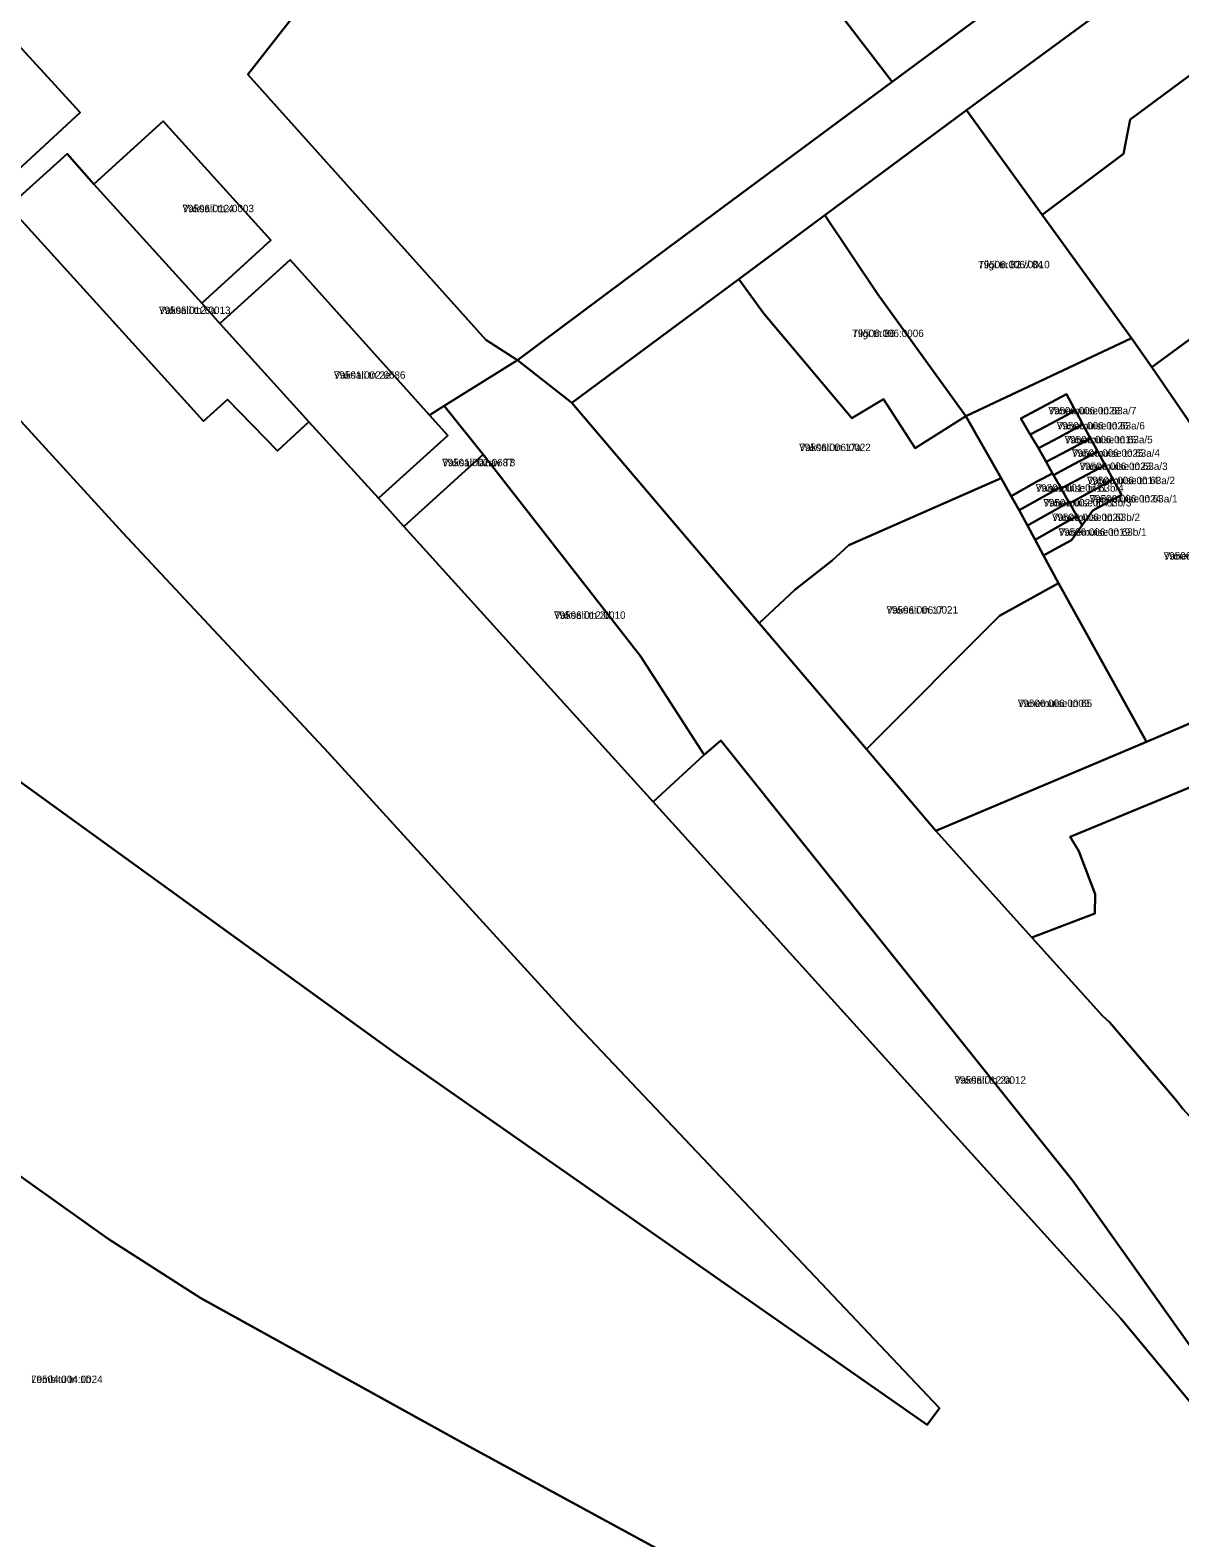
# Model space of a CAD drawing. Extents: x 643847 to 663718, y 6468443 to 6482775.
# Drawn here: x 658356.7 to 658589.8, y 6473255.6 to 6473561.4 of the extents above; entities that cross this region are included whole.
import ezdxf

# ---------------------------------------------------------------- set-up
doc = ezdxf.new("R2010")
doc.units = 0
for name, color, linetype in [('L_AADRESS', 7, 'Continuous'), ('PIIR', 7, 'Continuous'), ('TUNNUS', 7, 'Continuous')]:
    doc.layers.add(name, color=color, linetype=linetype)

msp = doc.modelspace()

# ---------------------------------------------------------------- linework, layer by layer
at = {"layer": 'PIIR'}
for points in [[(658099.05, 6473750.83), (658151.22, 6473704.05), (658244.25, 6473602.92), (658338.37, 6473500.05), (658375.52, 6473459.45), (658417.14, 6473414.88), (658466.64, 6473360.53), (658541.04, 6473281.9), (658538.55, 6473278.55), (658431.43, 6473353.39), (658331.84, 6473425.43), (658302.17, 6473447.92), (658262.57, 6473482.37), (658235.33, 6473509.39), (658193.26, 6473561.37), (658156.4, 6473618.75), (658128.89, 6473663.26), (658084.14, 6473738.99)], [(658099.05, 6473750.83), (658084.14, 6473738.99), (658128.89, 6473663.26), (658156.4, 6473618.75), (658193.26, 6473561.37), (658235.33, 6473509.39), (658262.57, 6473482.37), (658302.17, 6473447.92), (658331.84, 6473425.43), (658431.43, 6473353.39), (658538.55, 6473278.55), (658541.04, 6473281.9), (658466.64, 6473360.53), (658417.14, 6473414.88), (658375.52, 6473459.45), (658338.37, 6473500.05), (658244.25, 6473602.92), (658151.22, 6473704.05)], [(658618.85, 6473614.88), (658643.21, 6473632.41), (658650.48, 6473639.87), (658656.84, 6473626.22), (658646.06, 6473618.28), (658632.45, 6473608.26), (658596.39, 6473581.8), (658546.58, 6473545.17), (658517.84, 6473523.87), (658500.37, 6473510.91), (658466.51, 6473485.81), (658455.5, 6473494.46), (658486.16, 6473517.32), (658531.46, 6473550.91), (658557.16, 6473569.99), (658611.19, 6473609.32)], [(658557.16, 6473569.99), (658531.46, 6473550.91), (658503.12, 6473587.99), (658507.61, 6473591.43), (658515.13, 6473597.31), (658510.36, 6473604.43), (658501.33, 6473615.04), (658492.87, 6473608.18), (658480.69, 6473624.5), (658488.06, 6473630.64), (658500.14, 6473640.7), (658531.28, 6473602.28), (658540.97, 6473588.23), (658543.04, 6473589.14)], [(658486.16, 6473517.32), (658455.5, 6473494.46), (658449.11, 6473498.62), (658400.82, 6473552.42), (658413.74, 6473568.97), (658431.91, 6473585.5), (658447.86, 6473599.97), (658447.29, 6473603.25), (658456.64, 6473612.9), (658473.93, 6473628.35), (658476.14, 6473630.41), (658478.6, 6473627.29), (658480.69, 6473624.5), (658492.87, 6473608.18), (658498.85, 6473600.17), (658495.69, 6473597.71), (658503.12, 6473587.99), (658531.46, 6473550.91)], [(658275.56, 6473611.36), (658283.85, 6473618.78), (658301.93, 6473598.73), (658305.83, 6473602.18), (658313, 6473594.24), (658317.61, 6473598.5), (658366.83, 6473544.68), (658349.61, 6473528.79), (658347.37, 6473526.74), (658304.13, 6473573.95), (658307.09, 6473576.85)], [(658561.91, 6473523.92), (658546.58, 6473545.17), (658596.39, 6473581.8), (658618.51, 6473552.48), (658630.93, 6473536.03), (658636.59, 6473528.68), (658639.82, 6473523.94), (658646.92, 6473508.09), (658654.52, 6473491.09), (658633, 6473482.29), (658612.47, 6473473.9), (658612.19, 6473474.52), (658605.87, 6473488.59), (658592.12, 6473481.4), (658584.09, 6473493.04), (658618.72, 6473518.48), (658593.22, 6473553.32), (658579.74, 6473543.31), (658578.41, 6473536.32)], [(658579.97, 6473498.97), (658561.91, 6473523.92), (658578.41, 6473536.32), (658579.74, 6473543.31), (658593.22, 6473553.32), (658618.72, 6473518.48), (658584.09, 6473493.04)], [(658546.58, 6473545.17), (658561.91, 6473523.92), (658579.97, 6473498.97), (658546.39, 6473483.1), (658539.49, 6473492.62), (658528.52, 6473507.91), (658517.84, 6473523.87)], [(658383.67, 6473542.92), (658405.54, 6473518.82), (658391.54, 6473506.02), (658369.64, 6473530.2)], [(658352.42, 6473525.64), (658364.24, 6473536.3), (658369.64, 6473530.2), (658391.54, 6473506.02), (658395.19, 6473501.94), (658413.24, 6473482), (658406.86, 6473476.1), (658396.74, 6473486.49), (658391.88, 6473482.08)], [(658517.84, 6473523.87), (658528.52, 6473507.91), (658539.49, 6473492.62), (658546.39, 6473483.1), (658536.16, 6473476.66), (658529.69, 6473486.59), (658523.29, 6473482.68), (658505.4, 6473504.04), (658500.37, 6473510.91)], [(658413.24, 6473482), (658395.19, 6473501.94), (658409.46, 6473514.85), (658437.68, 6473483.32), (658441.39, 6473479.18), (658427.32, 6473466.48)], [(658504.49, 6473441.16), (658466.51, 6473485.81), (658500.37, 6473510.91), (658505.4, 6473504.04), (658523.29, 6473482.68), (658529.69, 6473486.59), (658536.16, 6473476.66), (658546.39, 6473483.1), (658553.57, 6473470.55), (658522.71, 6473456.93), (658519.31, 6473453.83), (658511.77, 6473447.88)], [(658559.47, 6473479.4), (658557.59, 6473482.67), (658566.8, 6473487.59), (658568.33, 6473484.78), (658568.62, 6473484.26), (658562.67, 6473481.11)], [(658441.39, 6473479.18), (658437.68, 6473483.32), (658440.66, 6473485.18), (658448.56, 6473475.31), (658432.48, 6473460.76), (658427.32, 6473466.48)], [(658561.17, 6473476.6), (658559.47, 6473479.4), (658562.67, 6473481.11), (658568.62, 6473484.26), (658570.16, 6473481.42), (658564.27, 6473478.26)], [(658562.68, 6473473.83), (658561.17, 6473476.6), (658564.27, 6473478.26), (658570.16, 6473481.42), (658571.67, 6473478.62), (658565.82, 6473475.48)], [(658564.2, 6473471.15), (658563.96, 6473471.52), (658562.68, 6473473.83), (658565.82, 6473475.48), (658571.67, 6473478.62), (658573.15, 6473475.96), (658567.3, 6473472.82)], [(658448.56, 6473475.31), (658480.45, 6473434.47), (658493.36, 6473414.41), (658483.05, 6473404.88), (658432.48, 6473460.76)], [(658565.74, 6473468.46), (658565.58, 6473468.7), (658564.2, 6473471.15), (658567.3, 6473472.82), (658573.15, 6473475.96), (658574.65, 6473473.21), (658568.8, 6473470.1)], [(658565.58, 6473468.7), (658557.2, 6473464.08), (658555.63, 6473466.92), (658561.09, 6473469.99), (658563.96, 6473471.52), (658564.2, 6473471.15)], [(658567.47, 6473465.44), (658567.32, 6473465.7), (658565.74, 6473468.46), (658568.8, 6473470.1), (658574.65, 6473473.21), (658576.28, 6473470.24), (658570.47, 6473467.08)], [(658526.24, 6473415.59), (658504.49, 6473441.16), (658511.77, 6473447.88), (658519.31, 6473453.83), (658522.71, 6473456.93), (658553.57, 6473470.55), (658555.63, 6473466.92), (658557.2, 6473464.08), (658558.91, 6473460.92), (658560.49, 6473458.02), (658562.19, 6473454.87), (658565.18, 6473449.26), (658553.23, 6473442.59)], [(658557.2, 6473464.08), (658565.58, 6473468.7), (658565.74, 6473468.46), (658567.32, 6473465.7), (658564.43, 6473464.07), (658558.91, 6473460.92)], [(658570, 6473461), (658568.94, 6473462.85), (658567.47, 6473465.44), (658570.47, 6473467.08), (658576.28, 6473470.24), (658577.98, 6473467.15), (658572.17, 6473463.97)], [(658560.49, 6473458.02), (658558.91, 6473460.92), (658564.43, 6473464.07), (658567.32, 6473465.7), (658567.47, 6473465.44), (658568.94, 6473462.85), (658566.04, 6473461.2)], [(658562.19, 6473454.87), (658560.49, 6473458.02), (658566.04, 6473461.2), (658568.94, 6473462.85), (658570, 6473461), (658567.83, 6473457.99), (658565.23, 6473456.53)], [(658540.35, 6473399), (658526.24, 6473415.59), (658553.23, 6473442.59), (658565.18, 6473449.26), (658583.03, 6473417.07)], [(658224.13, 6473429.38), (658277.31, 6473385.07), (658325.22, 6473349.95), (658372.55, 6473316.25), (658391.3, 6473304.26), (658445.73, 6473274.17), (658490.61, 6473249.76), (658508.51, 6473230.27), (658505.7, 6473227.37), (658510.07, 6473222.36), (658426.52, 6473144.68), (658414.12, 6473158.97), (658405.93, 6473161.83), (658402.61, 6473165.53), (658348.2, 6473226.27), (658238.43, 6473343.56), (658237.41, 6473343.53), (658232.66, 6473359), (658226.86, 6473377.18), (658218.17, 6473404.57), (658217.03, 6473407.59), (658209.79, 6473419.41)], [(658496.72, 6473417.32), (658568.09, 6473328.03), (658605.17, 6473275.88), (658601.3, 6473271.83), (658577.8, 6473300.21), (658483.05, 6473404.88), (658493.36, 6473414.41)], [(658630, 6473356.62), (658622.6, 6473349.34), (658626.92, 6473344.94), (658607.16, 6473324.91), (658598.83, 6473333.37), (658590.42, 6473342.6), (658588.95, 6473344.51), (658575.52, 6473360.24), (658574.14, 6473361.52), (658559.79, 6473377.4), (658572.54, 6473382.28), (658572.66, 6473386.18), (658569.3, 6473394.9), (658567.57, 6473397.77), (658604.84, 6473413.21)]]:
    msp.add_lwpolyline(points, close=True, dxfattribs=at)
for points in [[(658413.74, 6473568.97), (658400.82, 6473552.42), (658449.11, 6473498.62), (658455.5, 6473494.46), (658440.66, 6473485.18), (658437.68, 6473483.32), (658409.46, 6473514.85), (658395.19, 6473501.94), (658391.54, 6473506.02), (658405.54, 6473518.82), (658383.67, 6473542.92), (658369.64, 6473530.2), (658364.24, 6473536.3), (658352.42, 6473525.64), (658349.61, 6473528.79), (658366.83, 6473544.68), (658317.61, 6473598.5)], [(658352.42, 6473525.64), (658391.88, 6473482.08), (658396.74, 6473486.49), (658406.86, 6473476.1), (658413.24, 6473482), (658427.32, 6473466.48), (658432.48, 6473460.76), (658483.05, 6473404.88), (658577.8, 6473300.21), (658601.3, 6473271.83), (658617.93, 6473248.91), (658693.58, 6473165.93), (658667.09, 6473142.75), (658660.36, 6473146.34), (658618.09, 6473105.54), (658510.07, 6473222.36), (658505.7, 6473227.37), (658508.51, 6473230.27), (658490.61, 6473249.76), (658445.73, 6473274.17), (658391.3, 6473304.26), (658372.55, 6473316.25), (658325.22, 6473349.95)], [(658626.66, 6473435.57), (658583.03, 6473417.07), (658565.18, 6473449.26), (658562.19, 6473454.87), (658565.23, 6473456.53), (658567.83, 6473457.99), (658570, 6473461), (658572.17, 6473463.97), (658577.98, 6473467.15), (658576.28, 6473470.24), (658574.65, 6473473.21), (658573.15, 6473475.96), (658571.67, 6473478.62), (658570.16, 6473481.42), (658568.62, 6473484.26), (658568.33, 6473484.78), (658566.8, 6473487.59), (658557.59, 6473482.67), (658559.47, 6473479.4), (658561.17, 6473476.6), (658562.68, 6473473.83), (658563.96, 6473471.52), (658561.09, 6473469.99), (658555.63, 6473466.92), (658553.57, 6473470.55), (658546.39, 6473483.1), (658579.97, 6473498.97), (658584.09, 6473493.04), (658592.12, 6473481.4)], [(658605.17, 6473275.88), (658568.09, 6473328.03), (658496.72, 6473417.32), (658493.36, 6473414.41), (658480.45, 6473434.47), (658448.56, 6473475.31), (658440.66, 6473485.18), (658455.5, 6473494.46), (658466.51, 6473485.81), (658504.49, 6473441.16), (658526.24, 6473415.59), (658540.35, 6473399), (658559.79, 6473377.4), (658574.14, 6473361.52), (658575.52, 6473360.24), (658588.95, 6473344.51), (658590.42, 6473342.6)], [(658604.84, 6473413.21), (658567.57, 6473397.77), (658569.3, 6473394.9), (658572.66, 6473386.18), (658572.54, 6473382.28), (658559.79, 6473377.4), (658540.35, 6473399), (658583.03, 6473417.07), (658626.66, 6473435.57)]]:
    msp.add_lwpolyline(points, dxfattribs=at)

# ---------------------------------------------------------------- texts
at = {"layer": 'L_AADRESS'}
for s, p in [('Vaksali tn 4', (658387.59, 6473524.49)), ('Tiigi tn 82 // 84', (658548.91, 6473513.12)), ('Vaksali tn 6a', (658382.83, 6473503.85)), ('Tiigi tn 86', (658523.38, 6473499.16)), ('Vaksali tn 2e', (658418.29, 6473490.71)), ('Vanemuise tn 63a/7', (658563.15, 6473483.49)), ('Vanemuise tn 63a/6', (658564.86, 6473480.43)), ('Vaksali tn 17a', (658512.63, 6473476.04)), ('Vanemuise tn 63a/5', (658566.45, 6473477.62)), ('Vaksali tänav T8', (658440.24, 6473472.97)), ('Vanemuise tn 63a/4', (658567.92, 6473474.88)), ('Vanemuise tn 63a/3', (658569.47, 6473472.21)), ('Vanemuise tn 63a/2', (658570.98, 6473469.33)), ('Vanemuise tn 63b/4', (658560.57, 6473467.8)), ('Vanemuise tn 63b/3', (658562.13, 6473464.81)), ('Vanemuise tn 63a/1', (658571.49, 6473465.62)), ('Vanemuise tn 63b/2', (658563.88, 6473461.86)), ('Vanemuise tn 63b/1', (658565.21, 6473458.86)), ('Vanemuise tn 63', (658586.52, 6473454.03)), ('Vaksali tn 2d', (658462.92, 6473442.02)), ('Vaksali tn 17', (658530.32, 6473443.07)), ('Vanemuise tn 65', (658556.95, 6473424.13)), ('Vaksali tn 2a', (658544.11, 6473347.73)), ('Lembitu tn 1b', (658356.9, 6473287.03))]:
    msp.add_text(s, height=1.5, dxfattribs=at).set_placement(p)
at = {"layer": 'TUNNUS'}
for s, p in [('79506:012:0003', (658387.59, 6473524.49)), ('79506:006:0010', (658548.91, 6473513.12)), ('79506:012:0013', (658382.83, 6473503.85)), ('79506:006:0006', (658523.38, 6473499.16)), ('79501:002:0686', (658418.29, 6473490.71)), ('79506:006:0028', (658563.15, 6473483.49)), ('79506:006:0026', (658564.86, 6473480.43)), ('79506:006:0022', (658512.63, 6473476.04)), ('79506:006:0015', (658566.45, 6473477.62)), ('79501:002:0687', (658440.24, 6473472.97)), ('79506:006:0025', (658567.92, 6473474.88)), ('79506:006:0023', (658569.47, 6473472.21)), ('79506:006:0014', (658570.98, 6473469.33)), ('79301:001:0711', (658560.57, 6473467.8)), ('79501:002:0071', (658562.13, 6473464.81)), ('79506:006:0024', (658571.49, 6473465.62)), ('79506:006:0020', (658563.88, 6473461.86)), ('79506:006:0019', (658565.21, 6473458.86)), ('79506:006:0033', (658586.52, 6473454.03)), ('79506:012:0010', (658462.92, 6473442.02)), ('79506:006:0021', (658530.32, 6473443.07)), ('79506:006:0009', (658556.95, 6473424.13)), ('79506:012:0012', (658544.11, 6473347.73)), ('79504:004:0024', (658356.9, 6473287.03))]:
    msp.add_text(s, height=1.5, dxfattribs=at).set_placement(p)

doc.saveas('drawing.dxf')
